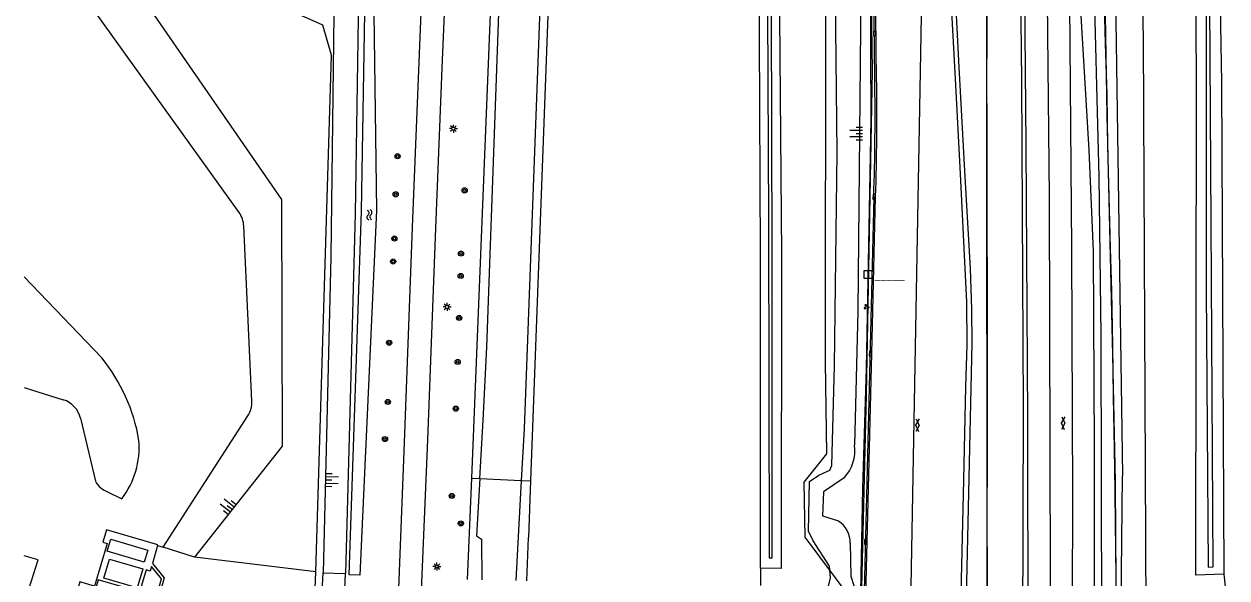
# Model space of a CAD drawing. Extents: x 133000 to 136000, y 400500 to 403500.
# Drawn here: x 133000 to 133187.9, y 401611.2 to 401697.7 of the extents above; entities that cross this region are included whole.
import ezdxf

# ---------------------------------------------------------------- set-up
doc = ezdxf.new("R2010")
doc.units = 0
for name, color, linetype in [('gg-afsc-hekwerk', 7, 'Continuous'), ('gg-afsc-lijn draadraster', 7, 'Continuous'), ('gg-afsc-lijn faunaraster', 7, 'Continuous'), ('gg-knt-BGT kruinlijn', 7, 'Continuous'), ('gg-knt-bovenkant onderkant talud', 7, 'Continuous'), ('gg-knt-verharding', 7, 'Continuous'), ('gg-kntw-bovenkant insteek waterloop', 7, 'Continuous'), ('gg-kntw-waterlijn', 7, 'Continuous'), ('gg-kwrk-gemaal', 7, 'Continuous'), ('gt-grn-vlakafsluiter', 7, 'Continuous'), ('gt-knt-geleideconstructie', 7, 'Continuous'), ('gt-symb-boom', 7, 'Continuous'), ('gt-symb-gesloten verharding', 7, 'Continuous'), ('gt-symb-groenvak', 7, 'Continuous'), ('gt-symb-hm paal', 7, 'Continuous'), ('gt-symb-kolk', 7, 'Continuous'), ('gt-symb-lichtmast', 7, 'Continuous'), ('gt-symb-talud symbool', 7, 'Continuous'), ('gt-symb-watersymbool', 7, 'Continuous'), ('gx-grn-maaiveld', 7, 'Continuous'), ('gx-knt-lijn weginrichtingselement', 7, 'Continuous')]:
    doc.layers.add(name, color=color, linetype=linetype)

# ---------------------------------------------------------------- blocks, each defined once
blk = doc.blocks.new('gt0-TALUD_1')
at = {"layer": 'gt-symb-talud symbool'}
for p, q in [((-1, -1), (-1, 0)), ((0.5, -2), (0.5, 0)), ((-0.5, -2), (-0.5, 0)), ((0, -1), (0, 0)), ((1, -1), (1, 0))]:
    blk.add_line(p, q, dxfattribs=at)
blk = doc.blocks.new('gt0-BOOM')
at = {"layer": 'gt-symb-boom'}
for radius in [0.4, 0.2]:
    blk.add_circle((0, 0), radius, dxfattribs=at)
blk = doc.blocks.new('gt0-LMAST')
at = {"layer": 'gt-symb-lichtmast'}
for p, q in [((-0.18, 0.17), (-0.45, 0.44)), ((-0.01, 0.25), (-0.01, 0.62)), ((0.17, 0.17), (0.44, 0.44)), ((-0.26, 0), (-0.63, 0)), ((-0.18, -0.18), (-0.45, -0.45)), ((-0.01, -0.25), (-0.01, -0.63)), ((0.44, -0.45), (0.17, -0.18)), ((0.24, 0), (0.62, 0))]:
    blk.add_line(p, q, dxfattribs=at)
blk.add_circle((-0.01, 0), 0.25, dxfattribs=at)
blk = doc.blocks.new('gt0-KOLK')
at = {"layer": 'gt-symb-kolk'}
blk.add_lwpolyline([(0, 0), (0.38, 0), (0.38, 0.4), (-0.37, 0.4), (-0.37, 0), (0, 0)], dxfattribs=at)
blk = doc.blocks.new('gt0-GRVAK')
at = {"layer": 'gt-symb-groenvak'}
for p, q in [((-0.11, 0.19), (-0.23, 0.24)), ((-0.18, 0.15), (0.09, 0.15)), ((-0.09, 0.21), (-0.16, 0.32)), ((-0.05, 0.21), (-0.05, 0.39)), ((0, 0.21), (0.06, 0.32)), ((0.01, 0.19), (0.13, 0.24)), ((0.26, -0.05), (0.2, 0.06)), ((0.3, -0.05), (0.3, 0.13)), ((0.35, -0.05), (0.41, 0.06)), ((-0.25, -0.23), (-0.36, -0.18)), ((-0.32, -0.26), (-0.05, -0.26)), ((-0.23, -0.21), (-0.29, -0.1)), ((-0.18, -0.2), (-0.18, -0.02)), ((-0.14, -0.21), (-0.07, -0.1)), ((-0.12, -0.23), (0, -0.18)), ((0.24, -0.07), (0.12, -0.02)), ((0.17, -0.11), (0.44, -0.11)), ((0.37, -0.07), (0.49, -0.02))]:
    blk.add_line(p, q, dxfattribs=at)
blk = doc.blocks.new('gt0-HMpaal')
at = {"layer": 'gt-symb-hm paal'}
blk.add_lwpolyline([(-0.6, 0.6), (0.6, 0.6), (0.6, -0.6), (-0.6, -0.6)], close=True, dxfattribs=at)
blk = doc.blocks.new('gt0-GESVH1')
at = {"layer": 'gt-symb-gesloten verharding'}
for p, q in [((-0.99, -0.26), (0.01, 0.24)), ((0.01, -0.26), (-0.99, 0.24)), ((0.01, 0.24), (1.01, -0.26)), ((1.01, 0.24), (0.01, -0.26))]:
    blk.add_line(p, q, dxfattribs=at)
blk = doc.blocks.new('gt0-WA')
at = {"layer": 'gt-symb-watersymbool'}
for centre, start, end in [((-0.32, 0.02), 28.0725, 151.9275), ((0.43, 0.42), 208.0725, 331.9275), ((-0.32, -0.43), 28.0725, 151.9275), ((0.43, -0.03), 208.0725, 331.9275)]:
    blk.add_arc(centre, 0.425, start, end, dxfattribs=at)

msp = doc.modelspace()

# ---------------------------------------------------------------- linework, layer by layer
at = {"layer": 'gg-afsc-hekwerk'}
for p, q in [((133026.64, 401614.44), (133021.73, 401615.99)), ((133045.55, 401612.17), (133026.64, 401614.44)), ((133043.96, 401569.48), (133045.55, 401612.17))]:
    msp.add_line(p, q, dxfattribs=at)
at = {"layer": 'gg-afsc-lijn draadraster'}
msp.add_lwpolyline([(133125.19, 401802.12), (133124.93, 401798.36), (133124.67, 401791.46), (133124.49, 401786.73), (133124.35, 401783.08), (133124.52, 401770.1), (133124.85, 401748.27), (133124.92, 401730.3), (133125.17, 401701.67), (133125.14, 401644.92), (133125.33, 401630.6), (133121.79, 401626.17), (133121.95, 401617.55), (133128.99, 401608.16)], dxfattribs=at)
at = {"layer": 'gg-afsc-lijn faunaraster'}
msp.add_lwpolyline([(133045.55, 401612.17), (133048.04, 401692.85), (133046.65, 401697.56), (133042.81, 401699.28), (133028.49, 401700.4), (133027.43, 401700.62)], dxfattribs=at)
at = {"layer": 'gg-knt-BGT kruinlijn'}
for p in [(133169.98, 401732.38), (133171.33, 401603.93)]:
    msp.add_line(p, (133171.56, 401627.12), dxfattribs=at)
for points in [[(133043.85, 402053.56), (133035.03, 401797.33), (133006.83, 401718.65), (133040.2, 401670.29), (133040.33, 401631.78), (133026.64, 401614.44)], [(133027.43, 401700.62), (133048.39, 401699.21), (133047.9, 401661.34), (133046.71, 401612.01)]]:
    msp.add_lwpolyline(points, dxfattribs=at)
at = {"layer": 'gg-knt-bovenkant onderkant talud'}
for p, q in [((133046.58, 401609.09), (133046.71, 401612.01)), ((133049.7, 401599.61), (133050.22, 401611.9))]:
    msp.add_line(p, q, dxfattribs=at)
msp.add_lwpolyline([(133054.59, 401816.46), (133052.72, 401772.66), (133027.38, 401717.29), (133028.58, 401705.61), (133048.5, 401704.12), (133052.23, 401702.08), (133051.71, 401668.05), (133050.22, 401611.9)], dxfattribs=at)
at = {"layer": 'gg-knt-verharding'}
for p, q in [((133138.47, 401606.08), (133140.76, 401731.03)), ((133132.71, 401670.74), (133131.16, 401606.34))]:
    msp.add_line(p, q, dxfattribs=at)
for points in [[(133056.16, 401553.13), (133058.15, 401600.18), (133059.41, 401632.35), (133060.68, 401666.01), (133062.71, 401716.34), (133063.74, 401742.9), (133064.51, 401761.2), (133065.51, 401787), (133066.6, 401815.69)], [(133070.12, 401815.59), (133069.19, 401787.4), (133067.31, 401742.16), (133066.35, 401716.57), (133065.26, 401690.83), (133064.24, 401665.82), (133063.01, 401632.77), (133061.66, 401600.54)], [(133144.86, 401731.22), (133144.93, 401726.27), (133144.98, 401726.24), (133145, 401716.76), (133145.12, 401708.53), (133145.21, 401706.25), (133146.01, 401690.99), (133146.95, 401673.84), (133147.74, 401659.55), (133147.99, 401653.11), (133148.01, 401647.86), (133147.07, 401605.77)], [(133132.87, 401689.18), (133132.57, 401715.72), (133132.52, 401725.39), (133132.8, 401725.41)], [(133133.14, 401689.2), (133132.83, 401715.72), (133132.8, 401725.41)], [(133131.41, 401606.33), (133132.41, 401646.25), (133132.99, 401670.74)]]:
    msp.add_lwpolyline(points, dxfattribs=at)
for centre, radius, start, end in [((132766.56, 401683.14), 366.35, 358.0608, 0.9448), ((132749.76, 401683.13), 383.43, 358.1493, 0.9066)]:
    msp.add_arc(centre, radius, start, end, dxfattribs=at)
at = {"layer": 'gg-kntw-bovenkant insteek waterloop'}
for p, q in [((133000, 401715.06), (133033.56, 401668.28)), ((133035.59, 401638.87), (133034.31, 401666.14)), ((133000, 401658.25), (133012.13, 401645.59)), ((133000, 401640.96), (133006.13, 401639.02)), ((133008.81, 401636.14), (133011.16, 401626.3)), ((133021.73, 401615.99), (133034.96, 401636.52)), ((133078.51, 401610.76), (133078.77, 401617.52)), ((133020.86, 401616.24), (133021.73, 401615.99))]:
    msp.add_line(p, q, dxfattribs=at)
for points in [[(133055.85, 401805.13), (133057.51, 401805.15), (133055.25, 401771.98), (133029.82, 401717.5), (133030.51, 401708.54), (133050.4, 401707.45), (133054.59, 401703.35), (133055.06, 401668.59), (133052.46, 401611.62), (133050.76, 401611.7), (133052.7, 401668.47), (133053.29, 401702.62), (133049.51, 401705.49), (133029.39, 401707.29), (133028.43, 401717.16), (133053.89, 401772.42), (133055.85, 401805.13)], [(133187.39, 401611.77), (133182.99, 401611.62), (133183.09, 401688.61), (133182.83, 401732.97)], [(133186.24, 401733.13), (133187.01, 401688.59), (133187.39, 401611.77)], [(133000, 401607.15), (133002.19, 401614.03), (133000, 401614.65)]]:
    msp.add_lwpolyline(points, dxfattribs=at)
for centre, radius, start, end in [((133030.31, 401665.95), 4.01, 2.7323, 35.6382), ((132990.21, 401627.95), 28.14, 9.6835, 38.8226), ((133004.92, 401635.21), 4, 13.4107, 72.4537), ((133031.6, 401638.68), 3.99, 327.1857, 2.7001), ((133004.54, 401631.65), 13.44, 322.9547, 4.3967), ((133014.23, 401627.9), 3.46, 207.4454, 251.5957)]:
    msp.add_arc(centre, radius, start, end, dxfattribs=at)
at = {"layer": 'gg-kntw-waterlijn'}
msp.add_lwpolyline([(133184.17, 401733.03), (133184.6, 401705.2), (133184.61, 401656.2), (133184.92, 401612.86), (133185.71, 401612.95), (133185.41, 401666.68), (133185.1, 401718.25), (133184.83, 401733.06)], dxfattribs=at)
at = {"layer": 'gg-kwrk-gemaal'}
for p, q in [((133018.54, 401612.61), (133017.67, 401609.64)), ((133019.05, 401612.46), (133018.18, 401609.49))]:
    msp.add_line(p, q, dxfattribs=at)
for points in [[(133020.86, 401616.24), (133020.89, 401616.36), (133012.85, 401618.72), (133012.29, 401616.78), (133012.96, 401616.59), (133011, 401609.92), (133008.73, 401610.59), (133007.93, 401607.84), (133009.67, 401607.33)], [(133013.54, 401617.24), (133019.31, 401615.54), (133018.77, 401613.68), (133012.99, 401615.38), (133013.54, 401617.24)], [(133020.86, 401616.24), (133020.04, 401613.43), (133021.89, 401611.19), (133021.36, 401609.36), (133019.1, 401608.69), (133011.58, 401610.9), (133010.93, 401608.72), (133010.58, 401608.82), (133010.11, 401607.2), (133009.67, 401607.33)], [(133017.67, 401609.64), (133012.45, 401611.17), (133013.32, 401614.14), (133018.54, 401612.61)], [(133018.18, 401609.49), (133019.24, 401609.18), (133021.08, 401609.76), (133021.46, 401611.07), (133019.9, 401612.96), (133019.7, 401612.27), (133019.05, 401612.46)]]:
    msp.add_lwpolyline(points, dxfattribs=at)
at = {"layer": 'gt-grn-vlakafsluiter'}
for p, q in [((133013.14, 401624.61), (133015.27, 401623.55)), ((133046.71, 401612.01), (133050.22, 401611.9))]:
    msp.add_line(p, q, dxfattribs=at)
at = {"layer": 'gt-knt-geleideconstructie'}
for points in [[(133128.62, 401875.34), (133130.75, 401806.78), (133131.58, 401751.68), (133132.43, 401690.41), (133131.52, 401639.81), (133130.58, 401601.1)], [(133150.39, 401601.31), (133150.43, 401613.33), (133150.45, 401637.3), (133150.45, 401649.3), (133150.4, 401673.3), (133150.37, 401697.36), (133150.34, 401709.33), (133150.26, 401721.38), (133150.19, 401733.25), (133150.06, 401745.26), (133149.85, 401757.25), (133149.78, 401769.27), (133149.52, 401781.24), (133149.36, 401793.24), (133149.08, 401805.22)], [(133170.63, 401604.72), (133170.55, 401612.75), (133170.46, 401619.42), (133170.39, 401624.77), (133170.3, 401631.43), (133170.13, 401639.5), (133170.03, 401647.47), (133169.86, 401656.03), (133169.69, 401662.7), (133169.48, 401670.77), (133169.28, 401678.7), (133169.13, 401686.71), (133168.92, 401694.69), (133168.71, 401702.68)]]:
    msp.add_lwpolyline(points, dxfattribs=at)
at = {"layer": 'gx-grn-maaiveld'}
for p, q in [((133076.88, 401799.41), (133069.86, 401626.77)), ((133085.55, 401798.98), (133079.1, 401626.35)), ((133069.86, 401626.77), (133069.21, 401610.97)), ((133069.86, 401626.77), (133071.17, 401626.71)), ((133071.17, 401626.71), (133077.63, 401626.42)), ((133077.63, 401626.42), (133076.78, 401610.79)), ((133077.63, 401626.42), (133079.1, 401626.35)), ((133079.1, 401626.35), (133078.77, 401617.52)), ((133115.02, 401612.74), (133115.02, 401610.01)), ((133187.39, 401611.77), (133187.86, 401607.47))]:
    msp.add_line(p, q, dxfattribs=at)
for points in [[(133071.17, 401626.71), (133071.69, 401635.84), (133072.25, 401647.24), (133076.69, 401770.36), (133078.32, 401787.32), (133078.75, 401796.9), (133079.44, 401797.31)], [(133082.44, 401797.33), (133083.01, 401797.26), (133083.49, 401796.43), (133083.52, 401794.75), (133081.72, 401730.95), (133078.08, 401634.49), (133077.63, 401626.42)], [(133155.32, 401731.7), (133155.79, 401688.86), (133156.03, 401637.82), (133155.81, 401567.36), (133155.58, 401525.69), (133155.25, 401500)], [(133167.28, 401732.25), (133166.98, 401708.45), (133167.84, 401673.86), (133168.17, 401649.1), (133168.25, 401604.04)], [(133173.96, 401732.56), (133174.77, 401695.5), (133175.21, 401605.81)], [(133115.02, 401612.74), (133115.04, 401661.88), (133114.72, 401729.83)], [(133117.71, 401729.97), (133118.3, 401661.71), (133118.24, 401612.68), (133115.02, 401612.74)], [(133115.97, 401729.89), (133116.04, 401710.86), (133116.29, 401667.21), (133116.39, 401614.36), (133116.85, 401614.34), (133116.85, 401662), (133116.74, 401699.78), (133116.48, 401729.91)], [(133125.57, 401609.72), (133125.97, 401611.2), (133125.81, 401613.03), (133123.24, 401617.01), (133122.52, 401618.5), (133122.66, 401626.25), (133124.15, 401627.23), (133125.82, 401628.04), (133126.15, 401628.78), (133126.56, 401644.35), (133126.97, 401677.63), (133126.66, 401706.85), (133125.86, 401730.35)], [(133130.44, 401730.56), (133130.34, 401721.44), (133130.63, 401697.1), (133130.24, 401652.88), (133129.69, 401631.95)], [(133071.17, 401626.71), (133070.65, 401617.75), (133071.45, 401617.26), (133071.47, 401610.91)], [(133128.06, 401626.82), (133124.85, 401624.66), (133124.7, 401620.91), (133127.2, 401620.09)], [(133129.01, 401616.6), (133129.13, 401611.48), (133130.07, 401608.58), (133130.04, 401607.42)]]:
    msp.add_lwpolyline(points, dxfattribs=at)
for centre, radius, start, end in [((133123.38, 401631.13), 6.37, 317.34, 7.3524), ((133125.07, 401616.77), 3.94, 357.5569, 57.2852)]:
    msp.add_arc(centre, radius, start, end, dxfattribs=at)
at = {"layer": 'gx-knt-lijn weginrichtingselement'}
for points in [[(133154.88, 401442.09), (133155.73, 401479.91), (133156.3, 401523.56), (133156.59, 401560.96), (133156.8, 401601.27), (133156.75, 401636.03), (133156.51, 401678.76), (133156.02, 401731.73)], [(133159.46, 401731.89), (133160.08, 401670.74), (133160.27, 401611.21), (133159.99, 401562.66), (133159.39, 401500.92), (133158.29, 401442.93)], [(133163.16, 401732.06), (133163.3, 401728.16), (133164.41, 401709.5), (133166.28, 401678.01), (133166.95, 401662.21), (133167.14, 401631.53), (133167.16, 401588.09), (133166.81, 401537.5), (133165.96, 401479.36), (133165.35, 401442.18)], [(133168.8, 401434.32), (133169.15, 401455.42), (133169.73, 401491.66), (133170.4, 401537.46), (133170.7, 401583.77), (133170.44, 401626.24), (133170.06, 401646), (133169.16, 401683.49), (133168.48, 401724.03), (133168.31, 401732.3)], [(133131.97, 401730.5), (133132.02, 401718), (133132.16, 401704.62), (133132.26, 401682.85), (133132, 401668.75), (133131.5, 401643.89), (133130.94, 401625.21), (133130.61, 401608.93), (133129.5, 401567.99), (133128.52, 401519.43), (133127.81, 401476.18), (133127.19, 401439.54)], [(133144.22, 401731.19), (133144.3, 401709.25), (133145.42, 401689.13), (133146.22, 401674.29), (133147.18, 401654.28), (133147.23, 401647.59), (133147.01, 401641.07), (133146.72, 401626.51), (133146.3, 401608.71), (133145.58, 401576.14), (133144.71, 401531.76), (133143.56, 401479.39), (133142.53, 401434.3)], [(133150.52, 401577.96), (133150.4, 401628.8), (133150.38, 401669.61), (133150.4, 401715.01), (133150.03, 401731.52)], [(133162.06, 401451.55), (133163.21, 401519.05), (133163.65, 401574.71), (133163.77, 401623.91), (133163.63, 401662.68), (133163.18, 401719.97)]]:
    msp.add_lwpolyline(points, dxfattribs=at)

# ---------------------------------------------------------------- block references
at = {"layer": 'gt-symb-boom'}
for p in [(133058.34, 401677.07), (133058.04, 401671.11), (133068.81, 401671.74), (133057.84, 401664.21), (133068.24, 401661.85), (133057.64, 401660.62), (133068.19, 401658.37), (133067.95, 401651.81), (133057.02, 401647.93), (133067.72, 401644.93), (133056.81, 401638.68), (133067.43, 401637.63), (133056.37, 401632.88), (133066.8, 401624), (133068.22, 401619.71)]:
    msp.add_blockref('gt0-BOOM', p, dxfattribs=at)
at = {"layer": 'gt-symb-gesloten verharding', "rotation": -92.46466335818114}
for p in [(133139.56, 401635.05), (133162.31, 401635.37)]:
    msp.add_blockref('gt0-GESVH1', p, dxfattribs=at)
at = {"layer": 'gt-symb-groenvak'}
msp.add_blockref('gt0-GRVAK', (133131.54, 401653.56), dxfattribs=at)
at = {"layer": 'gt-symb-hm paal'}
msp.add_blockref('gt0-HMpaal', (133131.8, 401658.59), dxfattribs=at)
at = {"layer": 'gt-symb-kolk'}
for p, rotation in [((133133.07, 401696.24), 90.7021387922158), ((133132.99, 401670.74), 88.84600809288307), ((133132.41, 401646.25), 88.65220763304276), ((133131.67, 401616.83), 88.55539994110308)]:
    msp.add_blockref('gt0-KOLK', p, dxfattribs=dict(at, rotation=rotation))
at = {"layer": 'gt-symb-lichtmast'}
for p in [(133067.07, 401681.37), (133066.08, 401653.53), (133064.48, 401612.98)]:
    msp.add_blockref('gt0-LMAST', p, dxfattribs=at)
at = {"layer": 'gt-symb-talud symbool', "rotation": -90.00000000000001}
msp.add_blockref('gt0-TALUD_1', (133130.97, 401680.62), dxfattribs=at)
at = {"layer": 'gt-symb-talud symbool'}
for p, xscale, yscale, rotation in [((133047.08, 401626.47), 1.0003379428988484, 1.0003379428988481, 88.5106452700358), ((133032.53, 401621.9), 0.9996929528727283, 0.9996929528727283, -128.2570168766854)]:
    msp.add_blockref('gt0-TALUD_1', p, dxfattribs=dict(at, xscale=xscale, yscale=yscale, rotation=rotation))
at = {"layer": 'gt-symb-watersymbool', "rotation": -81.60242742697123}
msp.add_blockref('gt0-WA', (133053.94, 401667.96), dxfattribs=at)

# ---------------------------------------------------------------- texts
at = {"layer": 'gt-symb-hm paal'}
msp.add_text('_____', height=1.25, dxfattribs=at).set_placement((133132.88, 401657.98))

doc.saveas('drawing.dxf')
